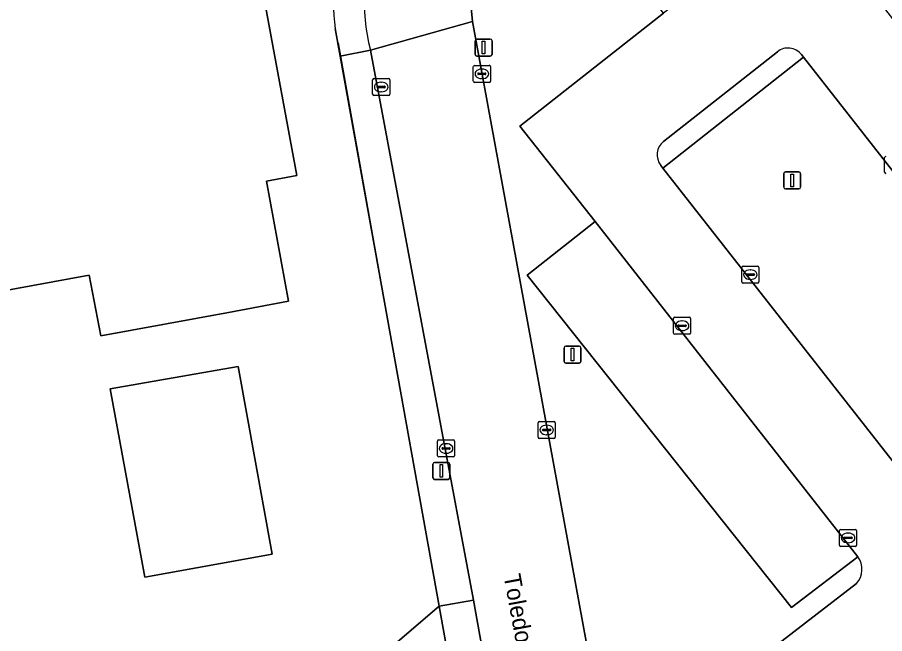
# Model space of a CAD drawing. Extents: x 159451 to 160664, y 388402 to 389723.
# Drawn here: x 159647.4 to 159698.3, y 388928.2 to 388964.3 of the extents above; entities that cross this region are included whole.
import ezdxf

# ---------------------------------------------------------------- set-up
doc = ezdxf.new("R2010")
doc.units = 0
for name, color, linetype in [('IMGEO_Erf', 7, 'Continuous'), ('IMGEO_Groenvoorziening', 7, 'Continuous'), ('IMGEO_Haag', 7, 'Continuous'), ('IMGEO_Kolk', 7, 'Continuous'), ('IMGEO_Lichtmast', 7, 'Continuous'), ('IMGEO_Muur', 7, 'Continuous'), ('IMGEO_Openbare_ruimte_label', 7, 'Continuous'), ('IMGEO_Pand', 7, 'Continuous'), ('IMGEO_Parkeervlak_open', 7, 'Continuous'), ('IMGEO_Rijbaan_lokaal_open', 7, 'Continuous'), ('IMGEO_Voetpad_open', 7, 'Continuous')]:
    doc.layers.add(name, color=color, linetype=linetype)

msp = doc.modelspace()

# ---------------------------------------------------------------- linework, layer by layer
at = {"layer": 'IMGEO_Erf'}
for points in [[(159646.405, 389032.016), (159648.46, 389020.775), (159649.759, 389013.67), (159658.567, 388965.49), (159661.814, 388966.062), (159663.838, 388955.065), (159662.061, 388954.736), (159663.353, 388947.682), (159659.823, 388947.031), (159652.347, 388945.664), (159651.669, 388949.218), (159616.15, 388942.714)], [(159672.185, 388929.801), (159668.807, 388948.609), (159666.381, 388962.068), (159666.09, 388963.685)], [(159611.805, 388918.556), (159649.975, 388924.443), (159659.557, 388918.986), (159672.185, 388929.801)]]:
    msp.add_lwpolyline(points, dxfattribs=at)
msp.add_lwpolyline([(159652.896, 388942.557), (159660.394, 388943.862), (159662.396, 388932.857), (159654.924, 388931.504)], close=True, dxfattribs=at)
msp.add_arc((159679.967, 388965.547), 14.001, 138.8882, 187.6411, dxfattribs=at)
at = {"layer": 'IMGEO_Groenvoorziening'}
for points in [[(159677.354, 388949.22), (159681.326, 388952.353), (159676.913, 388957.959), (159685.35, 388964.585), (159680.101, 388971.355), (159674.011, 388966.473), (159674.026, 388965.31), (159674.135, 388964.086), (159681.28, 388925.163), (159681.485, 388924.154), (159681.757, 388923.679), (159682.943, 388922.674), (159684.703, 388921.908), (159696.655, 388931.126)], [(159692.022, 388962.322), (159685.349, 388957.057)], [(159685.182, 388955.655), (159685.307, 388955.495), (159693.55, 388961.999), (159693.429, 388962.154)], [(159696.731, 388932.701), (159692.847, 388929.716), (159677.354, 388949.22)]]:
    msp.add_lwpolyline(points, dxfattribs=at)
for centre, radius, start, end in [((159692.642, 388961.536), 1.001, 38.1134, 128.2685), ((159685.969, 388956.272), 1, 128.3193, 218.0951), ((159695.752, 388931.959), 1.229, 317.3198, 37.155)]:
    msp.add_arc(centre, radius, start, end, dxfattribs=at)
at = {"layer": 'IMGEO_Haag'}
for points in [[(159692.022, 388962.322), (159685.349, 388957.057)], [(159685.182, 388955.655), (159685.307, 388955.495), (159693.55, 388961.999), (159693.429, 388962.154)]]:
    msp.add_lwpolyline(points, dxfattribs=at)
for centre, radius, start, end in [((159692.642, 388961.536), 1.001, 38.1134, 128.2685), ((159685.969, 388956.272), 1, 128.3193, 218.0951)]:
    msp.add_arc(centre, radius, start, end, dxfattribs=at)
at = {"layer": 'IMGEO_Kolk'}
for p, q in [((159674.19, 388960.595), (159674.19, 388961.447)), ((159674.265, 388961.521), (159675.117, 388961.521)), ((159674.678, 388961.301), (159674.703, 388961.301)), ((159675.191, 388961.447), (159675.191, 388960.595)), ((159674.449, 388961.015), (159674.449, 388961.027)), ((159674.887, 388960.978), (159674.489, 388960.978)), ((159674.492, 388961.064), (159674.89, 388961.064)), ((159674.933, 388961.027), (159674.933, 388961.015)), ((159668.285, 388959.824), (159668.285, 388960.676)), ((159668.36, 388960.75), (159669.212, 388960.75)), ((159668.544, 388960.244), (159668.544, 388960.256)), ((159668.587, 388960.293), (159668.985, 388960.293)), ((159668.773, 388960.53), (159668.798, 388960.53)), ((159669.028, 388960.256), (159669.028, 388960.244)), ((159669.286, 388960.676), (159669.286, 388959.824)), ((159675.117, 388960.521), (159674.265, 388960.521)), ((159674.701, 388960.741), (159674.676, 388960.741)), ((159669.212, 388959.75), (159668.36, 388959.75)), ((159668.982, 388960.207), (159668.584, 388960.207)), ((159668.796, 388959.97), (159668.771, 388959.97)), ((159698.312, 388955.257), (159698.312, 388956.109)), ((159689.935, 388948.82), (159689.935, 388949.672)), ((159690.01, 388949.746), (159690.862, 388949.746)), ((159690.936, 388949.672), (159690.936, 388948.82)), ((159690.194, 388949.24), (159690.194, 388949.252)), ((159690.632, 388949.203), (159690.234, 388949.203)), ((159690.237, 388949.289), (159690.635, 388949.289)), ((159690.423, 388949.526), (159690.448, 388949.526)), ((159690.678, 388949.252), (159690.678, 388949.24)), ((159690.862, 388948.746), (159690.01, 388948.746)), ((159690.446, 388948.966), (159690.421, 388948.966)), ((159685.934, 388945.822), (159685.934, 388946.674)), ((159686.009, 388946.748), (159686.861, 388946.748)), ((159686.422, 388946.528), (159686.447, 388946.528)), ((159686.935, 388946.674), (159686.935, 388945.822)), ((159686.193, 388946.242), (159686.193, 388946.254)), ((159686.631, 388946.205), (159686.233, 388946.205)), ((159686.236, 388946.291), (159686.634, 388946.291)), ((159686.677, 388946.254), (159686.677, 388946.242)), ((159686.861, 388945.748), (159686.009, 388945.748)), ((159686.445, 388945.968), (159686.42, 388945.968)), ((159677.992, 388939.712), (159677.992, 388940.564)), ((159678.067, 388940.638), (159678.919, 388940.638)), ((159678.48, 388940.418), (159678.505, 388940.418)), ((159678.993, 388940.564), (159678.993, 388939.712)), ((159678.251, 388940.132), (159678.251, 388940.144)), ((159678.689, 388940.095), (159678.291, 388940.095)), ((159678.294, 388940.181), (159678.692, 388940.181)), ((159678.735, 388940.144), (159678.735, 388940.132)), ((159672.092, 388938.627), (159672.092, 388939.479)), ((159672.167, 388939.553), (159673.019, 388939.553)), ((159673.093, 388939.479), (159673.093, 388938.627)), ((159678.919, 388939.638), (159678.067, 388939.638)), ((159678.503, 388939.858), (159678.478, 388939.858)), ((159672.351, 388939.047), (159672.351, 388939.059)), ((159672.789, 388939.01), (159672.391, 388939.01)), ((159672.394, 388939.096), (159672.792, 388939.096)), ((159672.58, 388939.333), (159672.605, 388939.333)), ((159672.835, 388939.059), (159672.835, 388939.047)), ((159673.019, 388938.553), (159672.167, 388938.553)), ((159672.603, 388938.773), (159672.578, 388938.773)), ((159695.741, 388934.306), (159696.593, 388934.306)), ((159695.666, 388933.38), (159695.666, 388934.232)), ((159695.925, 388933.8), (159695.925, 388933.812)), ((159695.968, 388933.849), (159696.366, 388933.849)), ((159696.154, 388934.086), (159696.179, 388934.086)), ((159696.409, 388933.812), (159696.409, 388933.8)), ((159696.667, 388934.232), (159696.667, 388933.38)), ((159696.593, 388933.306), (159695.741, 388933.306)), ((159696.363, 388933.763), (159695.965, 388933.763)), ((159696.177, 388933.526), (159696.152, 388933.526))]:
    msp.add_line(p, q, dxfattribs=at)
for points in [[(159674.19, 388960.595), (159674.19, 388961.447)], [(159674.265, 388961.521), (159675.117, 388961.521)], [(159675.191, 388961.447), (159675.191, 388960.595)], [(159668.285, 388959.824), (159668.285, 388960.676)], [(159668.36, 388960.75), (159669.212, 388960.75)], [(159669.286, 388960.676), (159669.286, 388959.824)], [(159675.117, 388960.521), (159674.265, 388960.521)], [(159669.212, 388959.75), (159668.36, 388959.75)], [(159698.312, 388955.257), (159698.312, 388956.109)], [(159689.935, 388948.82), (159689.935, 388949.672)], [(159690.01, 388949.746), (159690.862, 388949.746)], [(159690.936, 388949.672), (159690.936, 388948.82)], [(159690.862, 388948.746), (159690.01, 388948.746)], [(159685.934, 388945.822), (159685.934, 388946.674)], [(159686.009, 388946.748), (159686.861, 388946.748)], [(159686.935, 388946.674), (159686.935, 388945.822)], [(159686.861, 388945.748), (159686.009, 388945.748)], [(159677.992, 388939.712), (159677.992, 388940.564)], [(159678.067, 388940.638), (159678.919, 388940.638)], [(159678.993, 388940.564), (159678.993, 388939.712)], [(159672.092, 388938.627), (159672.092, 388939.479)], [(159672.167, 388939.553), (159673.019, 388939.553)], [(159673.093, 388939.479), (159673.093, 388938.627)], [(159678.919, 388939.638), (159678.067, 388939.638)], [(159673.019, 388938.553), (159672.167, 388938.553)], [(159695.741, 388934.306), (159696.593, 388934.306)], [(159695.666, 388933.38), (159695.666, 388934.232)], [(159696.667, 388934.232), (159696.667, 388933.38)], [(159696.593, 388933.306), (159695.741, 388933.306)]]:
    msp.add_lwpolyline(points, dxfattribs=at)
for centre, radius, start, end in [((159674.267, 388961.445), 0.0765, 91.552, 178.448), ((159674.267, 388961.445), 0.0765, 91.552, 178.448), ((159675.115, 388961.445), 0.0765, 1.552, 88.448), ((159675.115, 388961.445), 0.0765, 1.552, 88.448), ((159674.489, 388961.024), 0.0403, 85.8775, 175.7526), ((159674.486, 388961.014), 0.0366, 178.938, 274.7102), ((159674.89, 388961.021), 0.043, 264.8664, 352.4533), ((159674.894, 388961.026), 0.0386, 1.7309, 96.639), ((159668.362, 388960.674), 0.0765, 91.552, 178.448), ((159668.362, 388960.674), 0.0765, 91.552, 178.448), ((159668.584, 388960.253), 0.0403, 85.8775, 175.7526), ((159668.581, 388960.243), 0.0366, 178.938, 274.7102), ((159668.985, 388960.25), 0.043, 264.8664, 352.4533), ((159668.989, 388960.255), 0.0386, 1.7309, 96.639), ((159669.21, 388960.674), 0.0765, 1.552, 88.448), ((159669.21, 388960.674), 0.0765, 1.552, 88.448), ((159674.267, 388960.597), 0.0765, 181.552, 268.448), ((159674.267, 388960.597), 0.0765, 181.552, 268.448), ((159675.115, 388960.597), 0.0765, 271.552, 358.448), ((159675.115, 388960.597), 0.0765, 271.552, 358.448), ((159668.362, 388959.826), 0.0765, 181.552, 268.448), ((159668.362, 388959.826), 0.0765, 181.552, 268.448), ((159669.21, 388959.826), 0.0765, 271.552, 358.448), ((159669.21, 388959.826), 0.0765, 271.552, 358.448), ((159698.389, 388956.107), 0.0765, 91.552, 178.448), ((159698.389, 388956.107), 0.0765, 91.552, 178.448), ((159698.389, 388955.259), 0.0765, 181.552, 268.448), ((159698.389, 388955.259), 0.0765, 181.552, 268.448), ((159690.012, 388949.67), 0.0765, 91.552, 178.448), ((159690.012, 388949.67), 0.0765, 91.552, 178.448), ((159690.86, 388949.67), 0.0765, 1.552, 88.448), ((159690.86, 388949.67), 0.0765, 1.552, 88.448), ((159690.234, 388949.249), 0.0403, 85.8775, 175.7526), ((159690.231, 388949.239), 0.0366, 178.938, 274.7102), ((159690.635, 388949.246), 0.043, 264.8664, 352.4533), ((159690.639, 388949.251), 0.0386, 1.7309, 96.639), ((159690.012, 388948.822), 0.0765, 181.552, 268.448), ((159690.012, 388948.822), 0.0765, 181.552, 268.448), ((159690.86, 388948.822), 0.0765, 271.552, 358.448), ((159690.86, 388948.822), 0.0765, 271.552, 358.448), ((159686.011, 388946.672), 0.0765, 91.552, 178.448), ((159686.011, 388946.672), 0.0765, 91.552, 178.448), ((159686.859, 388946.672), 0.0765, 1.552, 88.448), ((159686.859, 388946.672), 0.0765, 1.552, 88.448), ((159686.233, 388946.251), 0.0403, 85.8775, 175.7526), ((159686.23, 388946.241), 0.0366, 178.938, 274.7102), ((159686.634, 388946.248), 0.043, 264.8664, 352.4533), ((159686.638, 388946.253), 0.0386, 1.7309, 96.639), ((159686.011, 388945.824), 0.0765, 181.552, 268.448), ((159686.011, 388945.824), 0.0765, 181.552, 268.448), ((159686.859, 388945.824), 0.0765, 271.552, 358.448), ((159686.859, 388945.824), 0.0765, 271.552, 358.448), ((159678.069, 388940.562), 0.0765, 91.552, 178.448), ((159678.069, 388940.562), 0.0765, 91.552, 178.448), ((159678.917, 388940.562), 0.0765, 1.552, 88.448), ((159678.917, 388940.562), 0.0765, 1.552, 88.448), ((159678.291, 388940.141), 0.0403, 85.8775, 175.7526), ((159678.288, 388940.131), 0.0366, 178.938, 274.7102), ((159678.692, 388940.138), 0.043, 264.8664, 352.4533), ((159678.696, 388940.143), 0.0386, 1.7309, 96.639), ((159672.169, 388939.477), 0.0765, 91.552, 178.448), ((159672.169, 388939.477), 0.0765, 91.552, 178.448), ((159673.017, 388939.477), 0.0765, 1.552, 88.448), ((159673.017, 388939.477), 0.0765, 1.552, 88.448), ((159678.069, 388939.714), 0.0765, 181.552, 268.448), ((159678.069, 388939.714), 0.0765, 181.552, 268.448), ((159678.917, 388939.714), 0.0765, 271.552, 358.448), ((159678.917, 388939.714), 0.0765, 271.552, 358.448), ((159672.391, 388939.056), 0.0403, 85.8775, 175.7526), ((159672.388, 388939.046), 0.0366, 178.938, 274.7102), ((159672.792, 388939.053), 0.043, 264.8664, 352.4533), ((159672.796, 388939.058), 0.0386, 1.7309, 96.639), ((159672.169, 388938.629), 0.0765, 181.552, 268.448), ((159672.169, 388938.629), 0.0765, 181.552, 268.448), ((159673.017, 388938.629), 0.0765, 271.552, 358.448), ((159673.017, 388938.629), 0.0765, 271.552, 358.448), ((159695.743, 388934.23), 0.0765, 91.552, 178.448), ((159695.743, 388934.23), 0.0765, 91.552, 178.448), ((159696.591, 388934.23), 0.0765, 1.552, 88.448), ((159696.591, 388934.23), 0.0765, 1.552, 88.448), ((159695.965, 388933.809), 0.0403, 85.8775, 175.7526), ((159695.962, 388933.799), 0.0366, 178.938, 274.7102), ((159696.366, 388933.806), 0.043, 264.8664, 352.4533), ((159696.37, 388933.811), 0.0386, 1.7309, 96.639), ((159695.743, 388933.382), 0.0765, 181.552, 268.448), ((159695.743, 388933.382), 0.0765, 181.552, 268.448), ((159696.591, 388933.382), 0.0765, 271.552, 358.448), ((159696.591, 388933.382), 0.0765, 271.552, 358.448)]:
    msp.add_arc(centre, radius, start, end, dxfattribs=at)
for centre, major_axis, ratio, start_param, end_param in [((159674.677, 388961.021), (-0.387, 0.002), 0.722429, 4.712389, 7.853982), ((159674.702, 388961.021), (-0.39, 0.002), 0.717154, 1.570796, 4.712389), ((159668.772, 388960.25), (-0.387, 0.002), 0.722429, 4.712389, 7.853982), ((159668.797, 388960.25), (-0.39, 0.002), 0.717154, 1.570796, 4.712389), ((159690.422, 388949.246), (-0.387, 0.002), 0.722429, 4.712389, 7.853982), ((159690.447, 388949.246), (-0.39, 0.002), 0.717154, 1.570796, 4.712389), ((159686.421, 388946.248), (-0.387, 0.002), 0.722429, 4.712389, 7.853982), ((159686.446, 388946.248), (-0.39, 0.002), 0.717154, 1.570796, 4.712389), ((159678.479, 388940.138), (-0.387, 0.002), 0.722429, 4.712389, 7.853982), ((159678.504, 388940.138), (-0.39, 0.002), 0.717154, 1.570796, 4.712389), ((159672.579, 388939.053), (-0.387, 0.002), 0.722429, 4.712389, 7.853982), ((159672.604, 388939.053), (-0.39, 0.002), 0.717154, 1.570796, 4.712389), ((159696.153, 388933.806), (-0.387, 0.002), 0.722429, 4.712389, 7.853982), ((159696.178, 388933.806), (-0.39, 0.002), 0.717154, 1.570796, 4.712389)]:
    msp.add_ellipse(centre, major_axis=major_axis, ratio=ratio, start_param=start_param, end_param=end_param, dxfattribs=at)
at = {"layer": 'IMGEO_Lichtmast'}
for p, q in [((159674.296, 388962.164), (159674.296, 388962.964)), ((159674.296, 388962.964), (159674.296, 388962.164)), ((159674.396, 388963.064), (159675.186, 388963.064)), ((159675.186, 388963.064), (159674.396, 388963.064)), ((159675.286, 388962.964), (159675.286, 388962.164)), ((159675.286, 388962.164), (159675.286, 388962.964)), ((159675.186, 388962.064), (159674.396, 388962.064)), ((159674.396, 388962.064), (159675.186, 388962.064)), ((159692.396, 388954.373), (159692.396, 388955.173)), ((159692.396, 388955.173), (159692.396, 388954.373)), ((159692.496, 388955.273), (159693.286, 388955.273)), ((159693.286, 388955.273), (159692.496, 388955.273)), ((159693.386, 388955.173), (159693.386, 388954.373)), ((159693.386, 388954.373), (159693.386, 388955.173)), ((159693.286, 388954.273), (159692.496, 388954.273)), ((159692.496, 388954.273), (159693.286, 388954.273)), ((159679.614, 388945.059), (159680.404, 388945.059)), ((159680.404, 388945.059), (159679.614, 388945.059)), ((159679.514, 388944.159), (159679.514, 388944.959)), ((159679.514, 388944.959), (159679.514, 388944.159)), ((159680.504, 388944.959), (159680.504, 388944.159)), ((159680.504, 388944.159), (159680.504, 388944.959)), ((159680.404, 388944.059), (159679.614, 388944.059)), ((159679.614, 388944.059), (159680.404, 388944.059)), ((159671.818, 388937.335), (159671.818, 388938.135)), ((159671.818, 388938.135), (159671.818, 388937.335)), ((159671.918, 388938.235), (159672.708, 388938.235)), ((159672.708, 388938.235), (159671.918, 388938.235)), ((159672.808, 388938.135), (159672.808, 388937.335)), ((159672.808, 388937.335), (159672.808, 388938.135)), ((159672.708, 388937.235), (159671.918, 388937.235)), ((159671.918, 388937.235), (159672.708, 388937.235))]:
    msp.add_line(p, q, dxfattribs=at)
for points in [[(159674.716, 388962.939), (159674.866, 388962.939), (159674.866, 388962.189), (159674.716, 388962.189), (159674.716, 388962.939)], [(159692.816, 388955.148), (159692.966, 388955.148), (159692.966, 388954.398), (159692.816, 388954.398), (159692.816, 388955.148)], [(159679.934, 388944.934), (159680.084, 388944.934), (159680.084, 388944.184), (159679.934, 388944.184), (159679.934, 388944.934)], [(159672.238, 388938.11), (159672.388, 388938.11), (159672.388, 388937.36), (159672.238, 388937.36), (159672.238, 388938.11)]]:
    msp.add_lwpolyline(points, dxfattribs=at)
for centre, start, end in [((159674.396, 388962.964), 90, 180), ((159674.396, 388962.964), 90, 180), ((159675.186, 388962.964), 0, 90), ((159675.186, 388962.964), 360, 90), ((159674.396, 388962.164), 180, 270), ((159674.396, 388962.164), 180, 270), ((159675.186, 388962.164), 270, 0), ((159675.186, 388962.164), 270, 0), ((159692.496, 388955.173), 90, 180), ((159692.496, 388955.173), 90, 180), ((159693.286, 388955.173), 0, 90), ((159693.286, 388955.173), 360, 90), ((159692.496, 388954.373), 180, 270), ((159692.496, 388954.373), 180, 270), ((159693.286, 388954.373), 270, 0), ((159693.286, 388954.373), 270, 0), ((159679.614, 388944.959), 90, 180), ((159679.614, 388944.959), 90, 180), ((159680.404, 388944.959), 0, 90), ((159680.404, 388944.959), 360, 90), ((159679.614, 388944.159), 180, 270), ((159679.614, 388944.159), 180, 270), ((159680.404, 388944.159), 270, 0), ((159680.404, 388944.159), 270, 0), ((159671.918, 388938.135), 90, 180), ((159671.918, 388938.135), 90, 180), ((159672.708, 388938.135), 0, 90), ((159672.708, 388938.135), 360, 90), ((159671.918, 388937.335), 180, 270), ((159671.918, 388937.335), 180, 270), ((159672.708, 388937.335), 270, 0), ((159672.708, 388937.335), 270, 0)]:
    msp.add_arc(centre, 0.1, start, end, dxfattribs=at)
at = {"layer": 'IMGEO_Muur'}
msp.add_lwpolyline([(159666.256, 388962.836), (159668.807, 388948.609)], dxfattribs=at)
at = {"layer": 'IMGEO_Pand'}
msp.add_lwpolyline([(159616.15, 388942.714), (159651.669, 388949.218), (159652.347, 388945.664), (159659.823, 388947.031), (159663.353, 388947.682), (159662.061, 388954.736), (159663.838, 388955.065), (159661.814, 388966.062), (159658.567, 388965.49), (159657.911, 388965.294), (159654.675, 388983.049), (159653.814, 388982.885), (159649.022, 389010.328), (159647.987, 389010.149), (159647.42, 389013.176), (159648.01, 389013.284), (159646.697, 389020.449)], dxfattribs=at)
msp.add_lwpolyline([(159652.896, 388942.557), (159654.924, 388931.504), (159662.396, 388932.857), (159660.394, 388943.862)], close=True, dxfattribs=at)
at = {"layer": 'IMGEO_Parkeervlak_open'}
for points in [[(159685.307, 388955.495), (159700.749, 388935.8), (159709.063, 388942.213), (159693.55, 388961.999)], [(159677.354, 388949.22), (159692.847, 388929.716), (159696.731, 388932.701), (159681.326, 388952.353)]]:
    msp.add_lwpolyline(points, close=True, dxfattribs=at)
at = {"layer": 'IMGEO_Rijbaan_lokaal_open'}
for points in [[(159717.636, 388939.965), (159721.61, 388943.099), (159721.454, 388943.297), (159721.011, 388943.858), (159720.34, 388944.716), (159720.186, 388944.913), (159716.209, 388941.803), (159693.567, 388970.994), (159692.452, 388981.005), (159688.872, 388978.174), (159690.5, 388968.629), (159686.769, 388965.699), (159685.35, 388964.585), (159676.913, 388957.959), (159681.326, 388952.353), (159696.731, 388932.701)], [(159668.152, 388962.408), (159674.135, 388964.086), (159674.026, 388965.31), (159674.011, 388966.473)], [(159681.28, 388925.163), (159674.135, 388964.086), (159668.152, 388962.408), (159674.192, 388930.162), (159675.645, 388922.073)], [(159685.349, 388957.057), (159692.022, 388962.322)], [(159693.429, 388962.154), (159693.55, 388961.999), (159709.063, 388942.213), (159709.182, 388942.061)], [(159685.307, 388955.495), (159685.182, 388955.655)], [(159700.878, 388935.636), (159700.749, 388935.8), (159685.307, 388955.495)], [(159696.655, 388931.126), (159684.703, 388921.908), (159682.943, 388922.674), (159681.757, 388923.679), (159681.485, 388924.154), (159683.633, 388912.346)]]:
    msp.add_lwpolyline(points, dxfattribs=at)
for centre, radius, start, end in [((159680.09, 388965.407), 12.309, 127.5926, 194.1013), ((159692.642, 388961.536), 1.001, 38.1134, 128.2685), ((159685.969, 388956.272), 1, 128.3193, 218.0951), ((159695.752, 388931.959), 1.229, 317.3198, 37.155)]:
    msp.add_arc(centre, radius, start, end, dxfattribs=at)
at = {"layer": 'IMGEO_Voetpad_open'}
for points in [[(159666.09, 388963.685), (159666.381, 388962.068), (159668.152, 388962.408)], [(159665.856, 388835.05), (159662.982, 388848.818), (159669.854, 388852.057), (159677.571, 388856.044), (159671.949, 388858.84), (159669.328, 388860.143), (159670.093, 388855.423), (159660.961, 388851.556), (159659.66, 388858.946), (159667.257, 388872.925), (159663.993, 388891.631), (159666.069, 388891.98), (159665.114, 388897.31), (159663.007, 388896.85), (159662.479, 388899.798), (159659.598, 388915.741), (159661.539, 388917.368), (159672.732, 388926.753), (159672.283, 388929.255), (159672.185, 388929.801), (159659.557, 388918.986), (159649.975, 388924.443), (159611.805, 388918.556)]]:
    msp.add_lwpolyline(points, dxfattribs=at)
for points in [[(159668.152, 388962.408), (159666.381, 388962.068), (159668.807, 388948.609), (159672.185, 388929.801), (159674.192, 388930.162)], [(159674.192, 388930.162), (159672.185, 388929.801), (159672.283, 388929.255), (159672.732, 388926.753), (159674.043, 388919.607), (159674.131, 388919.128), (159676.123, 388919.495), (159675.645, 388922.073)]]:
    msp.add_lwpolyline(points, close=True, dxfattribs=at)
for centre, radius, start, end in [((159680.09, 388965.407), 12.309, 127.5926, 194.1013), ((159679.967, 388965.547), 14.001, 138.8882, 187.6411)]:
    msp.add_arc(centre, radius, start, end, dxfattribs=at)

# ---------------------------------------------------------------- texts
at = {"layer": 'IMGEO_Openbare_ruimte_label'}
msp.add_text('Toledolaan', height=1, rotation=280.4894, dxfattribs=at).set_placement((159675.957, 388931.598))

doc.saveas('drawing.dxf')
